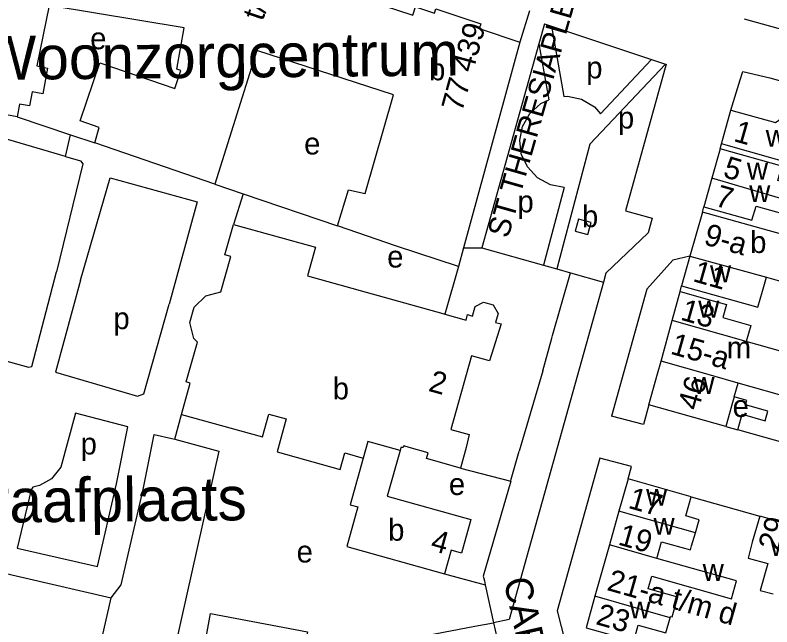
# Model space of a CAD drawing. Extents: x 157569 to 159501, y 382907 to 384670.
# Drawn here: x 158597.5 to 158735.9, y 383217.2 to 383329.1 of the extents above; entities that cross this region are included whole.
import ezdxf

# ---------------------------------------------------------------- set-up
doc = ezdxf.new("R2010")
doc.units = 0
for name, color, linetype in [('BLT_Basislijn', 7, 'Continuous'), ('BLT_Bebouwing', 7, 'Continuous'), ('BLT_Bebouwing_beschrifting', 7, 'Continuous'), ('BLT_Centroide', 7, 'Continuous'), ('BLT_Huisnummer', 7, 'Continuous'), ('BLT_Huisnummer_ tussenligend', 7, 'Continuous'), ('BLT_Huisnummer_reeks', 7, 'Continuous'), ('BLT_Onderverdeling_panden', 7, 'Continuous'), ('BLT_Straatnaam', 7, 'Continuous'), ('BLT_Straatnaam_verkleind', 7, 'Continuous'), ('BLT_Terrein_beschrifting', 7, 'Continuous')]:
    doc.layers.add(name, color=color, linetype=linetype)

msp = doc.modelspace()

# ---------------------------------------------------------------- linework, layer by layer
at = {"layer": 'BLT_Basislijn'}
for p, q in [((158694.25, 383327.51), (158693.23, 383323.88)), ((158694.25, 383327.51), (158695.55, 383327.08)), ((158730.79, 383328.42), (158882.99, 383285.93)), ((158695.55, 383327.08), (158697.82, 383314.2)), ((158695.55, 383327.08), (158713.86, 383321.01)), ((158693.23, 383323.88), (158682.78, 383286.53)), ((158693.23, 383323.88), (158695.05, 383313.6)), ((158713.86, 383321.01), (158704.51, 383311.08)), ((158713.86, 383321.01), (158716.38, 383320.17)), ((158716.38, 383320.17), (158702.59, 383305.53)), ((158716.55, 383320.12), (158709.09, 383293.3)), ((158716.38, 383320.17), (158716.55, 383320.12)), ((158597.83, 383310.49), (158607.59, 383307.22)), ((158606.67, 383303.22), (158589.14, 383308.43)), ((158606.67, 383303.22), (158607.59, 383307.22)), ((158607.59, 383307.22), (158612.05, 383305.72)), ((158702.59, 383305.53), (158696.51, 383282.67)), ((158726.38, 383304.62), (158726.64, 383305.59)), ((158633.95, 383298.21), (158639.13, 383296.44)), ((158697.87, 383297.59), (158694.08, 383283.35)), ((158639.13, 383296.44), (158637.37, 383290.83)), ((158639.13, 383296.44), (158656.4, 383290.54)), ((158709.09, 383293.3), (158713.98, 383291.98)), ((158723.14, 383293.07), (158723.44, 383294.01)), ((158713.98, 383291.98), (158713.23, 383289.28)), ((158679.46, 383286.55), (158682.78, 383286.53)), ((158682.78, 383286.53), (158694.08, 383283.35)), ((158678.52, 383283.13), (158676.02, 383274.42)), ((158719.07, 383278.56), (158719.35, 383279.57)), ((158693.94, 383264.05), (158695.59, 383269.99)), ((158693.94, 383264.05), (158689.66, 383249.35)), ((158626.65, 383251.5), (158627.85, 383256.07)), ((158727.42, 383253.84), (158729.63, 383253.24)), ((158626.65, 383251.5), (158634.68, 383249.35)), ((158634.68, 383249.35), (158624.69, 383204.52)), ((158678.92, 383246.22), (158688.09, 383243.82)), ((158721.08, 383241), (158733.63, 383237.46)), ((158676.01, 383226.9), (158683.42, 383224.88)), ((158683.42, 383224.88), (158684.95, 383217.89)), ((158611.64, 383207.59), (158615.03, 383222.48)), ((158684.95, 383217.89), (158688.83, 383200.67))]:
    msp.add_line(p, q, dxfattribs=at)
for points in [[(158691.5, 383329.91), (158689.78, 383324.19)], [(158728.34, 383311.75), (158730.03, 383317.29), (158730.55, 383318.82), (158735.51, 383317.65), (158888.01, 383274.78), (158889.65, 383274.38)], [(158697.82, 383314.2), (158698.45, 383314.27), (158701.05, 383313.73), (158703.43, 383312.34), (158704.51, 383311.08)], [(158697.87, 383297.59), (158695.38, 383298.04), (158693, 383299.32), (158691.13, 383301.33), (158690.03, 383303.75), (158689.75, 383306.21), (158690.24, 383308.76), (158691.57, 383311.14), (158693.61, 383312.97), (158695.05, 383313.6)], [(158606.67, 383303.22), (158609.43, 383302.47), (158609.85, 383301.89), (158605.03, 383282.14)], [(158609.42, 383280.64), (158614.86, 383299.34), (158630.77, 383294.96), (158625.63, 383276.22)], [(158713.23, 383289.28), (158705.51, 383281.87), (158705.06, 383280.27)], [(158584.44, 383287.9), (158580.99, 383272.2), (158580.74, 383269.99), (158599.91, 383264.7), (158600.51, 383264.82), (158605.03, 383282.14)], [(158720.88, 383285.02), (158717.72, 383284.25), (158713, 383278.98), (158706.52, 383255.76)], [(158694.08, 383283.35), (158696.51, 383282.67)], [(158695.59, 383269.99), (158695.74, 383270.51), (158699, 383281.97)], [(158696.51, 383282.67), (158699, 383281.97)], [(158699, 383281.97), (158705.06, 383280.27)], [(158609.42, 383280.64), (158604.82, 383263.78), (158619.83, 383259.41), (158620.96, 383259.83), (158625.63, 383276.22)], [(158705.06, 383280.27), (158687.8, 383218.5), (158684.95, 383217.89)], [(158713.33, 383257.83), (158712.39, 383254.23), (158706.52, 383255.76)], [(158615.97, 383243.36), (158618.08, 383253.8), (158608.49, 383256.26), (158605.78, 383246.42), (158604.1, 383244.25), (158601.9, 383243.02), (158600.68, 383242.75), (158600.4, 383242.24), (158597.83, 383231.61)], [(158615.03, 383222.48), (158616.86, 383224.87), (158620.86, 383242.3), (158622.89, 383252.39)], [(158622.89, 383252.39), (158626.13, 383251.64), (158626.65, 383251.5)], [(158688.09, 383243.82), (158688.19, 383244.19), (158689.66, 383249.35)], [(158704.36, 383248.06), (158696.56, 383220.14), (158699.5, 383208.66)], [(158709.57, 383244.28), (158710.16, 383246.54), (158704.36, 383248.06)], [(158612.5, 383228.2), (158615.97, 383243.36)], [(158688.09, 383243.82), (158683.08, 383226.48), (158683.27, 383225.58), (158683.42, 383224.88)], [(158569.38, 383233.38), (158583.35, 383229.84), (158615.03, 383222.48)], [(158597.83, 383231.61), (158612.5, 383228.2)], [(158643.86, 383165.76), (158645.61, 383178.25), (158658.74, 383177.55), (158659.44, 383177.9), (158663.7, 383200.72), (158666.01, 383212.43), (158666.63, 383214.47), (158672.94, 383215.66), (158681.54, 383217.29), (158684.95, 383217.89)]]:
    msp.add_lwpolyline(points, dxfattribs=at)
at = {"layer": 'BLT_Bebouwing'}
for p, q in [((158597.83, 383310.49), (158589.18, 383312.06)), ((158726.64, 383305.59), (158728.34, 383311.75)), ((158633.95, 383298.21), (158612.05, 383305.72)), ((158726.38, 383304.62), (158724.89, 383299.28)), ((158724.89, 383299.28), (158723.44, 383294.01)), ((158723.14, 383293.07), (158720.88, 383285.02)), ((158747.12, 383286.35), (158723.14, 383293.07)), ((158699.9, 383289.59), (158702.2, 383288.96)), ((158679.46, 383286.55), (158678.52, 383283.13)), ((158720.88, 383285.02), (158719.35, 383279.57)), ((158734.87, 383281.17), (158745.03, 383278.29)), ((158717.6, 383273.24), (158719.07, 383278.56)), ((158675.67, 383274.51), (158676.02, 383274.42)), ((158715.59, 383265.8), (158717.6, 383273.24)), ((158714.93, 383263.46), (158715.59, 383265.8)), ((158713.33, 383257.83), (158714.93, 383263.46)), ((158729.68, 383261.8), (158724.6, 383263.24)), ((158727.42, 383253.84), (158713.33, 383257.83)), ((158707.89, 383238.33), (158706.15, 383232.17)), ((158739.62, 383235.79), (158733.63, 383237.46)), ((158706.15, 383232.17), (158703.49, 383222.77)), ((158703.49, 383222.77), (158701.87, 383217.01))]:
    msp.add_line(p, q, dxfattribs=at)
for points in [[(158629.95, 383344.31), (158633.01, 383343.28), (158633.32, 383344.11), (158641.52, 383341.35), (158641.24, 383340.52), (158644.68, 383339.36), (158644.21, 383338.04), (158649.6, 383336.22), (158650.05, 383337.55), (158653.5, 383336.38), (158653.78, 383337.22), (158662.16, 383334.41), (158661.87, 383333.57), (158665.31, 383332.41), (158664.79, 383330.9), (158670.19, 383329.12), (158670.69, 383330.61), (158674.15, 383329.47), (158674.42, 383330.28), (158682.63, 383327.54), (158682.34, 383326.69), (158689.78, 383324.19)], [(158612.05, 383305.72), (158612.8, 383308.58), (158609.32, 383309.77), (158612.94, 383320.39), (158626.66, 383315.72), (158627.78, 383319), (158627.04, 383319.25), (158628.37, 383326.79), (158603.67, 383330.85), (158601.41, 383319.81), (158603.38, 383319.44), (158602.49, 383314.71), (158600.54, 383315.05), (158600.05, 383312.5), (158598.26, 383312.84), (158597.83, 383310.49)], [(158689.78, 383324.19), (158679.46, 383286.55)], [(158656.4, 383290.54), (158658.4, 383297.16), (158661.46, 383296.45), (158666.63, 383314.54), (158641.63, 383322.62), (158633.95, 383298.21)], [(158728.34, 383311.75), (158736.5, 383309.49), (158738.15, 383310.65), (158742.31, 383309.47), (158743.08, 383307.8)], [(158746.84, 383299.85), (158726.64, 383305.59)], [(158744.42, 383293.79), (158744.86, 383295.36), (158742.19, 383296.12), (158742.4, 383296.87), (158739.21, 383297.77), (158739.33, 383298.21), (158736.95, 383298.88), (158737.68, 383301.5), (158726.38, 383304.62)], [(158723.44, 383294.01), (158732.22, 383291.58), (158732.96, 383294.19), (158746.07, 383290.47), (158746.16, 383290.78), (158748.21, 383290.2)], [(158702.2, 383288.96), (158702.81, 383291.18), (158700.51, 383291.8), (158699.9, 383289.59)], [(158627.85, 383256.07), (158629.45, 383261.8), (158628.76, 383261.99), (158630.79, 383269.27), (158630.15, 383269.92), (158629.4, 383272.86), (158630.18, 383275.67), (158632.34, 383277.78), (158635.09, 383278.49), (158636.9, 383284.98), (158635.83, 383285.28), (158637.37, 383290.83)], [(158637.37, 383290.83), (158652.38, 383286.63), (158650.92, 383281.42), (158675.67, 383274.51)], [(158678.52, 383283.13), (158667.19, 383286.85), (158656.4, 383290.54)], [(158719.35, 383279.57), (158733.3, 383275.66), (158734.15, 383278.62), (158734.87, 383281.17)], [(158719.07, 383278.56), (158724.01, 383277.16), (158727.56, 383276.17), (158726.89, 383273.79), (158731.98, 383272.35), (158731.15, 383269.4)], [(158676.02, 383274.42), (158679.93, 383273.32), (158680.21, 383274.32), (158681.13, 383274.06), (158681.61, 383275.78), (158683.12, 383276.62), (158684.9, 383276.13), (158685.78, 383274.55), (158685.32, 383272.88), (158686.33, 383272.6)], [(158686.33, 383272.6), (158684.23, 383265.83), (158680.9, 383266.76), (158677.16, 383253.29), (158680.47, 383252.36), (158679.97, 383250), (158678.92, 383246.22)], [(158741.74, 383266.4), (158731.15, 383269.4)], [(158728.96, 383259.27), (158728.79, 383258.65), (158727.42, 383253.84)], [(158729.63, 383253.24), (158730.43, 383256.08), (158734.62, 383254.89), (158735.12, 383256.65), (158731.06, 383257.8), (158731.29, 383258.61), (158728.96, 383259.27)], [(158627.85, 383256.07), (158642.7, 383251.93), (158643.86, 383256.12), (158647.03, 383255.25)], [(158647.03, 383255.25), (158645.35, 383249.2), (158656.91, 383245.98), (158657.75, 383249.02), (158661.12, 383248.08)], [(158742.71, 383249.55), (158741.07, 383250), (158729.63, 383253.24)], [(158678.92, 383246.22), (158672.67, 383247.98), (158672.97, 383249.03), (158669.5, 383250), (158668.54, 383250.28), (158668.45, 383250), (158668.17, 383250.02), (158668.02, 383250), (158667.87, 383249.47)], [(158667.87, 383249.47), (158665.52, 383241.09), (158680.81, 383236.82), (158679.09, 383230.66), (158677.2, 383231.19), (158676.01, 383226.9)], [(158661.12, 383248.08), (158658.74, 383239.51), (158660.12, 383239.12), (158658.1, 383231.89), (158676.01, 383226.9)], [(158709.57, 383244.28), (158707.89, 383238.33)], [(158721.08, 383241), (158709.57, 383244.28)], [(158721.86, 383234.39), (158722.54, 383236.79), (158720.11, 383237.48), (158721.08, 383241)], [(158733.63, 383237.46), (158732.28, 383232.65), (158731.5, 383229.76), (158735.09, 383228.76), (158733.72, 383223.86), (158736.1, 383223.2)], [(158714.81, 383229.72), (158715.67, 383232.76), (158720.97, 383231.26), (158721.18, 383231.98), (158721.86, 383234.39)], [(158717.27, 383218.83), (158717.34, 383219.09), (158717.64, 383219), (158718.66, 383222.6), (158713.24, 383224.13), (158713.89, 383226.46), (158728.49, 383222.34), (158729.41, 383225.59), (158714.81, 383229.72)], [(158630.23, 383203.46), (158633.21, 383219.64), (158650.94, 383216.26), (158650.16, 383212), (158652.03, 383211.63), (158650.59, 383203.78), (158648.71, 383204.14), (158646.01, 383189.9), (158645.08, 383184.99), (158637.25, 383186.47), (158637.57, 383188.17), (158615.67, 383192.41), (158614.88, 383188.26)], [(158701.87, 383217.01), (158706.68, 383215.65), (158710.59, 383214.54), (158711.43, 383217.5), (158716.49, 383216.07), (158717.27, 383218.83)]]:
    msp.add_lwpolyline(points, dxfattribs=at)
at = {"layer": 'BLT_Onderverdeling_panden'}
for p, q in [((158720.88, 383285.02), (158734.87, 383281.17)), ((158731.15, 383269.4), (158717.6, 383273.24)), ((158724.6, 383263.24), (158715.59, 383265.8)), ((158728.96, 383259.27), (158729.68, 383261.8)), ((158721.86, 383234.39), (158707.89, 383238.33)), ((158714.81, 383229.72), (158706.15, 383232.17)), ((158717.27, 383218.83), (158703.49, 383222.77))]:
    msp.add_line(p, q, dxfattribs=at)
for points in [[(158744.42, 383293.79), (158744.34, 383293.52), (158724.89, 383299.28)], [(158741.74, 383266.4), (158739.65, 383258.98), (158729.68, 383261.8)], [(158667.87, 383249.47), (158661.96, 383251.1), (158661.12, 383248.08)]]:
    msp.add_lwpolyline(points, dxfattribs=at)

# ---------------------------------------------------------------- texts
at = {"layer": 'BLT_Bebouwing_beschrifting'}
msp.add_text('Woonzorgcentrum', height=8, rotation=0.5505, dxfattribs=at).set_placement((158591.27, 383317.24))
at = {"layer": 'BLT_Centroide'}
for s, p in [('e', (158611.18, 383322.87)), ('b', (158673.16, 383317.19)), ('p', (158701.91, 383317.53)), ('p', (158707.71, 383308.36)), ('w', (158734.73, 383305.03)), ('e', (158650.31, 383303.62)), ('w', (158731.29, 383299.03)), ('w', (158731.71, 383294.91)), ('p', (158689.33, 383293.03)), ('b', (158701.13, 383290.31)), ('b', (158731.89, 383285.59)), ('e', (158665.5, 383282.93)), ('w', (158724.54, 383280.25)), ('w', (158722.39, 383273.78)), ('p', (158615.43, 383271.65)), ('m', (158727.61, 383266.29)), ('b', (158655.54, 383258.81)), ('w', (158721.51, 383259.81)), ('e', (158728.67, 383255.59)), ('p', (158609.43, 383248.72)), ('e', (158676.78, 383241.31)), ('w', (158712.85, 383239.34)), ('b', (158665.68, 383232.95)), ('w', (158714.21, 383234.03)), ('e', (158648.93, 383228.96)), ('w', (158735.56, 383230.12)), ('w', (158723.2, 383225.59)), ('w', (158709.8, 383218.75))]:
    msp.add_text(s, height=4, dxfattribs=at).set_placement(p)
at = {"layer": 'BLT_Huisnummer'}
for s, rotation, p in [('1', 344.1732, (158728.69, 383306.1)), ('7', 344.1707, (158725.26, 383294.28)), ('11', 344.172, (158721.23, 383280.46)), ('46', 74.1711, (158722.4, 383256.6)), ('17', 344.2224, (158709.39, 383238.98)), ('29', 74.3793, (158737.12, 383230.9)), ('23', 344.2254, (158703.48, 383217.71))]:
    msp.add_text(s, height=4, rotation=rotation, dxfattribs=at).set_placement(p)
at = {"layer": 'BLT_Huisnummer_ tussenligend'}
for s, rotation, p in [('5', 343.1082, (158726.74, 383299.57)), ('13', 344.1761, (158718.97, 383273.42)), ('19', 344.2224, (158707.55, 383232.28))]:
    msp.add_text(s, height=4, rotation=rotation, dxfattribs=at).set_placement(p)
at = {"layer": 'BLT_Huisnummer_reeks'}
for s, rotation, p in [('t/m', 71.422, (158642.73, 383327.89)), ('77 439', 74.6638, (158679.19, 383311.27)), ('9-a', 344.1707, (158723.21, 383287.22)), ('15-a', 344.1723, (158717.12, 383267.19)), ('2', 344.3952, (158672.87, 383260.39)), ('4', 344.4066, (158673.24, 383231.23)), ('21-a t/m d', 344.2254, (158705.51, 383223.95))]:
    msp.add_text(s, height=4, rotation=rotation, dxfattribs=at).set_placement(p)
at = {"layer": 'BLT_Straatnaam'}
msp.add_text('CARMELITESSENSTRAAT', height=5, rotation=282.5969, dxfattribs=at).set_placement((158686.75, 383225.72))
at = {"layer": 'BLT_Straatnaam_verkleind'}
msp.add_text('ST THERESIAPLEIN', height=4, rotation=74.1453, dxfattribs=at).set_placement((158687.62, 383288.15))
at = {"layer": 'BLT_Terrein_beschrifting'}
msp.add_text('Begraafplaats', height=8, rotation=0.5505, dxfattribs=at).set_placement((158573.84, 383236.06))

doc.saveas('drawing.dxf')
